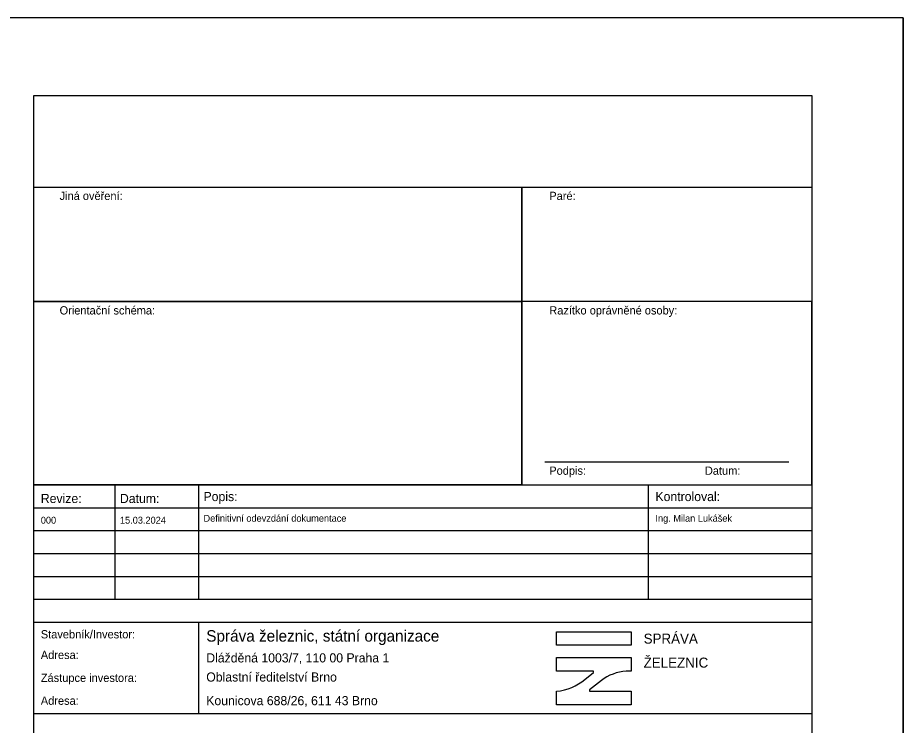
# Model space of a CAD drawing. Extents: x 2343 to 7744, y -5880 to 2050.
# Drawn here: x 5636.5 to 5830, y -5737.5 to -5583 of the extents above; entities that cross this region are included whole.
import ezdxf

# ---------------------------------------------------------------- set-up
doc = ezdxf.new("R2010")
doc.units = 0
for name, color, linetype in [('Default', 7, 'Continuous'), ('Rozpiska_Logo', 7, 'Continuous'), ('Rozpiska_pola_3', 7, 'Continuous'), ('Rozpiska_pole_1', 7, 'Continuous'), ('Rozpiska_pole_2', 7, 'Continuous'), ('Rozpiska_pole_4', 7, 'Continuous'), ('Rozpiska_pole_5', 7, 'Continuous'), ('Rozpiska_pole_6', 7, 'Continuous'), ('Vrstva 50', 7, 'Continuous')]:
    doc.layers.add(name, color=color, linetype=linetype)

msp = doc.modelspace()

# ---------------------------------------------------------------- linework, layer by layer
at = {"layer": 'Default'}
for p, q in [((5830, -5583), (5830, -5880)), ((5746.65, -5685), (5746.65, -5620))]:
    msp.add_line(p, q, dxfattribs=at)
at = {"layer": 'Rozpiska_Logo'}
for p, q in [((5760.4, -5727.47), (5762.34, -5726.01)), ((5762.34, -5726.01), (5762.34, -5725.66)), ((5764.03, -5727.74), (5761.42, -5729.76)), ((5761.42, -5729.76), (5761.42, -5730.07))]:
    msp.add_line(p, q, dxfattribs=at)
msp.add_lwpolyline([(5754.22, -5717.09), (5770.52, -5717.09), (5770.52, -5720.02), (5754.22, -5720.02)], close=True, dxfattribs=at)
for points in [[(5762.34, -5725.66), (5754.22, -5725.66), (5754.22, -5722.73), (5770.52, -5722.73), (5770.52, -5725.66), (5769.44, -5725.66)], [(5761.42, -5730.07), (5770.52, -5730.07), (5770.52, -5733), (5754.22, -5733), (5754.22, -5730.07), (5754.28, -5730.07)]]:
    msp.add_lwpolyline(points, dxfattribs=at)
for centre, radius, start, end in [((5753.44, -5719.58), 10.52, 274.6014, 311.4254), ((5770.18, -5735.68), 10.04, 94.2142, 127.7808)]:
    msp.add_arc(centre, radius, start, end, dxfattribs=at)
at = {"layer": 'Rozpiska_pola_3'}
msp.add_line((5751.65, -5680), (5805, -5680), dxfattribs=at)
at = {"layer": 'Rozpiska_pole_1'}
msp.add_lwpolyline([(5640, -5600), (5810, -5600), (5810, -5865), (5640, -5865)], close=True, dxfattribs=at)
at = {"layer": 'Rozpiska_pole_2'}
for points in [[(5640, -5620), (5746.65, -5620), (5746.65, -5645), (5640, -5645)], [(5746.65, -5620), (5810, -5620), (5810, -5645), (5746.65, -5645)], [(5640, -5645), (5746.65, -5645), (5746.65, -5685), (5640, -5685)], [(5810, -5645), (5746.65, -5645), (5746.65, -5685), (5810, -5685)]]:
    msp.add_lwpolyline(points, close=True, dxfattribs=at)
at = {"layer": 'Rozpiska_pole_4'}
for p, q in [((5657.78, -5710), (5657.78, -5685)), ((5676.05, -5710), (5676.05, -5685)), ((5774.3, -5710), (5774.3, -5685)), ((5640, -5690), (5810, -5690)), ((5640, -5695), (5810, -5695)), ((5640, -5700), (5810, -5700)), ((5640, -5705), (5810, -5705))]:
    msp.add_line(p, q, dxfattribs=at)
msp.add_lwpolyline([(5640, -5685), (5810, -5685), (5810, -5710), (5640, -5710)], close=True, dxfattribs=at)
at = {"layer": 'Rozpiska_pole_5'}
msp.add_line((5676.05, -5735), (5676.05, -5715), dxfattribs=at)
msp.add_lwpolyline([(5640, -5715), (5810, -5715), (5810, -5735), (5640, -5735)], close=True, dxfattribs=at)
at = {"layer": 'Vrstva 50'}
msp.add_lwpolyline([(4570, -5880), (5830, -5880), (5830, -5583), (4570, -5583)], close=True, dxfattribs=at)

# ---------------------------------------------------------------- texts
at = {"layer": 'Rozpiska_pola_3'}
for s, p in [('Paré:', (5752.65, -5622.8)), ('Razítko oprávněné osoby:', (5752.65, -5647.8)), ('Podpis:', (5752.65, -5682.8)), ('Datum:', (5786.65, -5682.8))]:
    msp.add_text(s, height=1.8, dxfattribs=at).set_placement(p)
at = {"layer": 'Rozpiska_pole_2'}
for s, p in [('Jiná ověření:', (5645.65, -5622.8)), ('Orientační schéma:', (5645.65, -5647.8))]:
    msp.add_text(s, height=1.8, dxfattribs=at).set_placement(p)
at = {"layer": 'Rozpiska_pole_4'}
for s, height, p in [('Revize:', 2, (5641.55, -5688.97)), ('Popis:', 2, (5677.1, -5688.55)), ('Kontroloval:', 2, (5775.85, -5688.55)), ('Datum:', 2, (5658.84, -5688.97)), ('000', 1.5, (5641.55, -5693.47)), ('15.03.2024', 1.5, (5658.84, -5693.47)), ('Definitivní odevzdání dokumentace', 1.5, (5677.1, -5693.05)), ('Ing. Milan Lukášek', 1.5, (5775.85, -5693.05))]:
    msp.add_text(s, height=height, dxfattribs=at).set_placement(p)
at = {"layer": 'Rozpiska_pole_5'}
for s, height, p in [('Stavebník/Investor:', 1.8, (5641.55, -5718.53)), ('Správa železnic, státní organizace', 2.5, (5677.7, -5719.23)), ('Adresa:', 1.8, (5641.55, -5723.03)), ('Zástupce investora:', 1.8, (5641.55, -5728.03)), ('Adresa:', 1.8, (5641.55, -5733.03))]:
    msp.add_text(s, height=height, dxfattribs=at).set_placement(p)
at = {"layer": 'Rozpiska_pole_6'}
for s, height, p in [('SPRÁVA', 2.183, (5773.27, -5719.67)), ('Dlážděná 1003/7, 110 00 Praha 1', 2, (5677.7, -5723.78)), ('ŽELEZNIC', 2.183, (5773.27, -5724.91)), ('Oblastní ředitelství Brno', 2, (5677.7, -5727.96)), ('Kounicova 688/26, 611 43 Brno', 2, (5677.7, -5733.12))]:
    msp.add_text(s, height=height, dxfattribs=at).set_placement(p)

doc.saveas('drawing.dxf')
